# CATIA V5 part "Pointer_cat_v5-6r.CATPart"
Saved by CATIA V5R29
Part number: Pointer
Bounding box of the stored display mesh (mm): x -9.942 to 9.942, y -9.942 to 9.942, z 0 to 100
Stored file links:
  C:\Users\CADCIM 00\Desktop\New folder (2)\c16\New folder\Cam Follower mechanism\Pointer_cat_v5-6r.CATPart
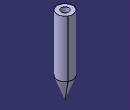
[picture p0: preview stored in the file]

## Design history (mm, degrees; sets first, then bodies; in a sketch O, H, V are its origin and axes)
Body1 (main body)
  Sketch1 on yz-plane, origin (0, 0, 0), H (0, 1, 0), V (0, 0, 1)
    line L1 (0, 0) -> (10, 27.4748)
    point P1 (10, 27.4748)
    line L2 (10, 27.4748) -> (10, 100)
    point P2 (10, 27.4748)
    point P3 (10, 100)
    point P4 (0, 100)
    point P5 (10, 91.3901)
    line L3 (0, 0) -> (0, 100)
    reference intersected line E1 through (0, 0) direction (-1, 0) from xy-plane
    reference intersected line E3 through (0, 0) direction (0, 1) from zx-plane
    line L4 (0, 100) -> (10, 100)
    point P6 (10, 100)
    angle L1 L3 = 20
    distance O P4 = 100
    length L4 = 10
    coincidence: P2 L1, P4 V, P5 L2, P2 P1, E3 P4, P1 L2, P6 L2, P6 P3
    vertical: L2 V, L3 V, E3 V
    horizontal: E1 H, L4 H
    perpendicularity: E1 L2
  Shaft1: profile Sketch1, axis Sketch1.L3, angle 360
  Sketch2 on face of Shaft1 from Sketch1.L4, origin (0, 0, 100), H (1, 0, 0), V (0, 1, 0)
    point P1 (0, 0)
  Hole1: placed by Sketch2, at (0, 0, 100) direction (0, 0, -1), diameter 10, depth 55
